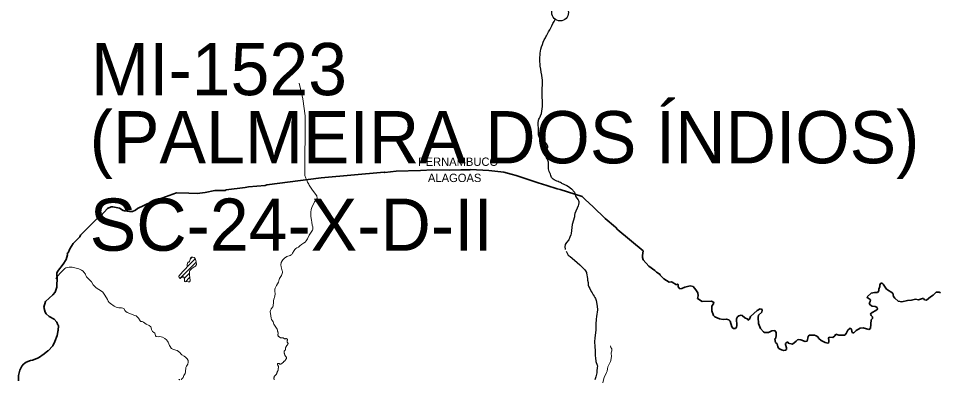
# Model space of a CAD drawing. Extents: x 553962 to 842807, y 8883888 to 9032388.
# Drawn here: x 608947 to 617774, y 8913066 to 8916524 of the extents above; entities that cross this region are included whole.
import ezdxf
from ezdxf.enums import TextEntityAlignment as Align

# ---------------------------------------------------------------- set-up
doc = ezdxf.new("R2010")
doc.units = 0
doc.header["$LTSCALE"] = 200
doc.linetypes.add('LONG_DASH_SHORT_DASH', pattern=[9.9, 6, -1.2, 1.5, -1.2])
doc.layers.add('6', color=7, linetype='Continuous', lineweight=13)

msp = doc.modelspace()

# ---------------------------------------------------------------- linework, layer by layer
at = {"layer": '6'}
for p, q in [((610565.7, 8914148.7), (610640.2, 8914223.2)), ((610592.8, 8914218.2), (610613.2, 8914238.6)), ((610494, 8914034.6), (610649.5, 8914190.1)), ((610536, 8914034.2), (610587.2, 8914085.3)), ((610547.2, 8914002.9), (610587.8, 8914043.4))]:
    msp.add_line(p, q, dxfattribs=at)
for points in [[(611636.1, 8915904.7), (611671, 8915753.7), (611694.2, 8915591.1), (611691.9, 8915020), (611701.8, 8914992.6)], [(611701.8, 8914992.6), (611709.5, 8914973.9), (611717.8, 8914957.2), (611728.7, 8914937.8), (611733.3, 8914927.2), (611738.5, 8914917.8), (611758.7, 8914890.3), (611784.6, 8914852.3), (611805.4, 8914826.5), (611808.3, 8914799.7), (611808.3, 8914799.7), (611808.3, 8914799.7), (611808.3, 8914799.7), (611785.5, 8914766.1), (611759.3, 8914712), (611752.6, 8914694.7), (611748.8, 8914667.4), (611748.6, 8914646.5), (611749.8, 8914628.6), (611755.2, 8914591.8), (611757.1, 8914572.4), (611762.5, 8914542.9), (611767.8, 8914528), (611767.7, 8914505.5), (611764.2, 8914496.9), (611758.8, 8914486.9), (611732.2, 8914447.5), (611716.2, 8914412.1), (611704.3, 8914394.9), (611693.1, 8914382.8), (611678.9, 8914371), (611658.2, 8914357.9), (611644, 8914347.7), (611629.4, 8914333.4), (611613.3, 8914326.6), (611603.6, 8914319.1), (611594.8, 8914310.6), (611588.4, 8914302.7), (611574.1, 8914274.6), (611566.6, 8914264.4), (611559.3, 8914258.5), (611551.8, 8914254.4), (611541, 8914251), (611528.6, 8914248.7), (611519.9, 8914244.7), (611496.5, 8914227.1), (611480.9, 8914211.8), (611472.7, 8914202), (611463.8, 8914186.4), (611462.7, 8914163.8), (611465.1, 8914144.4), (611472.2, 8914118.5), (611474.6, 8914105.9), (611476.2, 8914102), (611476.4, 8914091.2), (611475.1, 8914081.1), (611472.1, 8914071.7), (611467.5, 8914062.4), (611449.6, 8914032.3), (611446.1, 8914024.2), (611437.7, 8913996.9), (611420.2, 8913966.8), (611420.2, 8913966.8), (611408.7, 8913942.1), (611405.2, 8913932.8)], [(610550.1, 8914128.2), (610522.6, 8914099.6), (610485.2, 8914054.4), (610484.5, 8914051.4), (610485.8, 8914043.6), (610490.9, 8914038.7), (610495.7, 8914032.3), (610498.2, 8914032.8), (610503.2, 8914038.6), (610511.3, 8914041.6), (610520, 8914049.9), (610522.6, 8914050.8), (610526.2, 8914050.7), (610528.6, 8914048), (610536.9, 8914032.6), (610538.2, 8914010.4), (610539.8, 8914005.3), (610541.1, 8914003.4), (610572.1, 8914000.6), (610584.6, 8914001.8), (610587.4, 8914003), (610591.6, 8914010.9), (610591.8, 8914024.6), (610588.8, 8914032.4), (610588, 8914036.4), (610586.7, 8914070.3), (610587.8, 8914099.9), (610590.6, 8914109.6), (610593.7, 8914113.9), (610608, 8914127.7), (610618.3, 8914134.6), (610625.4, 8914140.7), (610632.9, 8914144.4), (610642.7, 8914150.8), (610652.1, 8914166.7), (610649.1, 8914194), (610643.6, 8914215.7), (610640.1, 8914223.4), (610630.2, 8914235.9), (610618.4, 8914238.7)], [(610618.4, 8914238.7), (610613.1, 8914238.6), (610606, 8914236.5), (610596.3, 8914228.7), (610594.6, 8914224.8), (610586.9, 8914195.9), (610580.3, 8914189.7), (610574.4, 8914190.9), (610570.6, 8914185.2), (610568.3, 8914176.6), (610564.4, 8914166.3), (610563.7, 8914158.5), (610565.8, 8914148.4), (610564.8, 8914145.3), (610550.1, 8914128.2)], [(609304.8, 8914031.3), (609316.3, 8914047), (609328.2, 8914061), (609345.4, 8914085), (609380.9, 8914119.9), (609391.6, 8914128.4), (609400.3, 8914134.1), (609417.9, 8914140.3)], [(609417.9, 8914140.3), (609432.3, 8914143), (609446.8, 8914143.1), (609462, 8914141.3), (609500.2, 8914133.9), (609525, 8914125.2), (609551.2, 8914114.5), (609565.8, 8914103.2), (609574.5, 8914094.8), (609590.7, 8914075.3), (609593.5, 8914063.3), (609599.2, 8914050.6), (609647.6, 8914002.6), (609664.4, 8913973.8), (609675.8, 8913959.2), (609691.7, 8913944.3), (609718.8, 8913929.2), (609744.3, 8913912.2), (609754.5, 8913902), (609775.4, 8913874.4), (609799.6, 8913831.8), (609808, 8913815.2), (609816.3, 8913803.9), (609827.9, 8913793.1), (609863.5, 8913769.2), (609883, 8913759.4), (609908.5, 8913753.4), (609934, 8913752.3), (609948.3, 8913750), (609960, 8913741.4), (609967.7, 8913728.2), (609976.3, 8913717.3), (609987.7, 8913708.8), (610063.1, 8913680.4), (610075.6, 8913674.7), (610087.9, 8913664), (610096.3, 8913653.3), (610112.7, 8913629.2), (610116, 8913625.7), (610120.4, 8913623.2), (610133.8, 8913620.9), (610145.7, 8913616.5), (610170.2, 8913594.9), (610199.2, 8913582.2), (610214.4, 8913569.6), (610219.3, 8913560.4), (610223.4, 8913545.4), (610230.4, 8913527.1), (610232.1, 8913525.3), (610240.4, 8913521), (610255.3, 8913511.4), (610259.1, 8913488.4), (610261.4, 8913484.1), (610266.4, 8913478.2), (610271.4, 8913476.7), (610286, 8913476.2), (610299.6, 8913477.2), (610314.8, 8913475.2), (610327.5, 8913471.4), (610351.4, 8913457.7), (610364.5, 8913445.8), (610374.8, 8913433.9), (610381.7, 8913423.5), (610381.7, 8913423.5), (610389.1, 8913409.2)], [(611405.2, 8913932.8), (611404.3, 8913919.3), (611405.3, 8913904.8), (611407.2, 8913893.3), (611407.4, 8913883.2), (611405, 8913868.1), (611400.2, 8913852.2), (611396.6, 8913845.8), (611394.4, 8913837.1), (611392.4, 8913819.2), (611392.1, 8913798.3), (611389.3, 8913781), (611388.7, 8913768.9), (611385.8, 8913762.7), (611369.2, 8913742.2), (611367.3, 8913738.6), (611366.3, 8913734.3), (611360.9, 8913727.5), (611358.2, 8913718), (611357.9, 8913713.9), (611361.9, 8913696.8), (611368.6, 8913655.1), (611372.9, 8913641.6), (611381.2, 8913629.6), (611387.6, 8913616.9), (611394.3, 8913594.7), (611425.5, 8913547), (611428, 8913539.7)], [(611428, 8913539.7), (611428.7, 8913537), (611429.4, 8913534.2), (611430, 8913531.7), (611431, 8913529.4), (611431.9, 8913527), (611432, 8913525.2), (611432.7, 8913522.8), (611433.4, 8913520.1), (611433.8, 8913517.5), (611434.4, 8913515), (611435.1, 8913512.4), (611435.7, 8913509.5), (611435.7, 8913506.8), (611435.5, 8913504.3), (611434.9, 8913501.7), (611434.3, 8913499.2), (611433.8, 8913496.3), (611433.7, 8913493.8), (611433.8, 8913491.1), (611434.6, 8913488.2), (611435.4, 8913485.7), (611436.1, 8913482.5), (611437.5, 8913480.3), (611439.4, 8913478.3), (611441.8, 8913477), (611444.5, 8913476.4), (611446.8, 8913474.9), (611448.8, 8913472.9), (611450.7, 8913470.9), (611452.7, 8913468.9), (611454.9, 8913467), (611457.3, 8913465.7), (611460.4, 8913464.9), (611463, 8913465.2), (611465.5, 8913465.8), (611468.2, 8913466.4), (611470.9, 8913466.6), (611473.5, 8913466.6), (611476.2, 8913466.6), (611478.8, 8913466.4), (611481.7, 8913466.1), (611484.9, 8913464.2), (611487.1, 8913462.7), (611489, 8913461), (611491.2, 8913459.4), (611493.2, 8913457.7), (611495.6, 8913456.4), (611498.5, 8913456), (611501.1, 8913456), (611503.7, 8913456.2), (611506.5, 8913456.8), (611509.3, 8913457.7), (611512, 8913458.6), (611514.6, 8913458.4), (611517.1, 8913457.1), (611519.3, 8913455.5), (611521.2, 8913453.8), (611522.9, 8913451.8), (611523.8, 8913450.6)], [(611523.8, 8913450.6), (611525.4, 8913446.9), (611525.5, 8913444), (611524.6, 8913441.6), (611522.9, 8913439.5), (611521.7, 8913437), (611520.6, 8913434.1), (611520.6, 8913431.2), (611520.6, 8913428.1), (611521.6, 8913425.5), (611523.2, 8913423.3), (611524.9, 8913421.3), (611526.6, 8913419.5), (611528.4, 8913417.5), (611530, 8913415.4), (611530.8, 8913412.9), (611530.7, 8913409.9), (611529.8, 8913407.3), (611528.4, 8913404.8), (611527.3, 8913402.4), (611526.1, 8913400.1), (611523.9, 8913398), (611521.4, 8913396.4), (611519.7, 8913394.6), (611518.1, 8913392.3), (611516.8, 8913389.9), (611515.6, 8913387.5), (611514.4, 8913385.1), (611512.9, 8913382.6), (611511.6, 8913380.2), (611510.4, 8913377.8), (611508.9, 8913374.4), (611507.9, 8913371.9), (611507.1, 8913369.3), (611506.2, 8913366.7), (611505.4, 8913364.2), (611505.2, 8913361.7), (611505.2, 8913359.2), (611505.4, 8913356.3), (611505.8, 8913353.8), (611505.5, 8913351.2), (611504.2, 8913348.8), (611502.8, 8913346.7), (611501.1, 8913344.8), (611498.7, 8913342.8), (611496.5, 8913341.3), (611494.8, 8913339.3), (611493.6, 8913337.1), (611493.5, 8913334.4), (611493.8, 8913331.9), (611493.8, 8913328.8), (611493.8, 8913326.2), (611493.8, 8913323.6), (611493.8, 8913320.8), (611494.2, 8913318), (611495.1, 8913315.3), (611496.4, 8913312.1), (611497.2, 8913309.5), (611498, 8913306.9), (611499.1, 8913304.3), (611500, 8913302), (611501.1, 8913299.2), (611502, 8913296.4), (611503.1, 8913293.8), (611504.4, 8913291.4)], [(610389.1, 8913409.2), (610395.4, 8913393.2), (610401.3, 8913381.1), (610409.7, 8913367.4), (610414, 8913362.1), (610427.1, 8913356), (610453.7, 8913346.8), (610468.8, 8913342.4), (610480.8, 8913335.7), (610492.2, 8913325.5), (610503.7, 8913311.6), (610513.8, 8913301.2), (610536.1, 8913288.8), (610548.6, 8913279.7), (610553.6, 8913275), (610564.1, 8913262.7), (610572.3, 8913247.7), (610574, 8913236.7), (610573.8, 8913232.5), (610569.3, 8913214.6), (610556.1, 8913194.1), (610551.1, 8913181.3), (610549.8, 8913168.7), (610549.5, 8913152.5), (610547.4, 8913140.6), (610543.5, 8913125.3), (610537.7, 8913112.6), (610533.2, 8913105.3), (610525.4, 8913084.2)], [(614620.1, 8913388.5), (614624.9, 8913373.7), (614631.9, 8913361.2), (614634.6, 8913353.9), (614634.5, 8913342.2), (614625.8, 8913322.2), (614625.8, 8913309.6), (614626.6, 8913305.2), (614628.8, 8913299.8), (614629, 8913291), (614622.6, 8913249.5), (614619.8, 8913237.7), (614614.5, 8913226.6), (614606.9, 8913214.3), (614596, 8913186.5), (614591, 8913166.9), (614587, 8913146.5), (614583.2, 8913134.8), (614574.9, 8913115.8), (614563.6, 8913095.4), (614555.5, 8913074.3), (614545.5, 8913034.2)], [(614620.1, 8913388.5), (614624.9, 8913373.7), (614631.9, 8913361.2), (614634.6, 8913353.9), (614634.5, 8913342.2), (614625.8, 8913322.2), (614625.8, 8913309.6), (614626.6, 8913305.2), (614628.8, 8913299.8), (614629, 8913291), (614622.6, 8913249.5), (614619.8, 8913237.7), (614614.5, 8913226.6), (614606.9, 8913214.3), (614596, 8913186.5), (614591, 8913166.9), (614587, 8913146.5), (614583.2, 8913134.8), (614574.9, 8913115.8), (614563.6, 8913095.4), (614555.5, 8913074.3), (614545.5, 8913034.2)], [(611504.4, 8913291.4), (611506.1, 8913289.1), (611507.8, 8913287.2), (611509.6, 8913285.3), (611511.5, 8913283), (611513.4, 8913280.6), (611515.3, 8913278.2), (611516.3, 8913275.7), (611516.2, 8913273.1), (611515.8, 8913270.5), (611515, 8913267.9), (611513.8, 8913265.1), (611512.2, 8913263), (611510.6, 8913260.8), (611509, 8913258.3), (611507.6, 8913255.6), (611505.9, 8913253), (611504.3, 8913251), (611502.6, 8913248.5), (611500.7, 8913246.3), (611498.7, 8913244.6), (611496.5, 8913242.9), (611494.1, 8913241.4), (611491.5, 8913239.6), (611489.4, 8913237.7), (611487.3, 8913235.2), (611485.6, 8913233), (611483.6, 8913230.5), (611481.8, 8913228.6), (611480, 8913226.6), (611478.2, 8913224.8), (611475.6, 8913222.2), (611473.4, 8913220.8), (611471.2, 8913219.4), (611468.9, 8913217.9), (611465.8, 8913216.3), (611463, 8913214.8)], [(611463, 8913214.8), (611460.6, 8913213.6), (611458, 8913212.7), (611455.2, 8913212.1), (611452.7, 8913212.4), (611450.5, 8913213.7), (611448.5, 8913215.6), (611446.8, 8913218), (611445.3, 8913220), (611441.8, 8913220.3), (611438.9, 8913220.2), (611436.2, 8913219.8), (611433.4, 8913219), (611431, 8913217.9), (611429.9, 8913215.5), (611429.9, 8913212.7), (611429.9, 8913210.1), (611430.6, 8913207.5), (611432.2, 8913205.1), (611433.5, 8913202.6), (611434.5, 8913200.1), (611435.5, 8913197.2), (611436.8, 8913194.7), (611438.5, 8913192.3), (611439.6, 8913189.6), (611440, 8913186.4), (611439.9, 8913183.7), (611439.6, 8913180.8), (611438.8, 8913178.3), (611437.8, 8913175.9), (611437.3, 8913173.3), (611436.7, 8913170.4), (611436.1, 8913167.8), (611435.5, 8913165), (611435.2, 8913162), (611435, 8913159.2), (611434.7, 8913154.3), (611434.7, 8913154.1), (611433.7, 8913152.4), (611432.9, 8913149.8), (611431.8, 8913147.4), (611430.2, 8913145.2), (611429, 8913143), (611427.7, 8913140.3), (611426.5, 8913137.7), (611425.6, 8913135), (611424.8, 8913132.1), (611424, 8913129.5), (611423.2, 8913127.1), (611422, 8913124.6), (611420.9, 8913122.1), (611420.1, 8913119.7), (611419, 8913117), (611417.4, 8913115), (611415.2, 8913113.4), (611413.2, 8913111.8), (611411.3, 8913110), (611409.6, 8913108.1), (611408.1, 8913105.9), (611406.4, 8913103.6), (611404.7, 8913101.5), (611402.4, 8913099.4), (611400.6, 8913097.7), (611398.9, 8913095.4), (611397.7, 8913092.6)], [(610492.6, 8913063.5), (610491.2, 8913065.9), (610489, 8913067.2), (610486.6, 8913066.3), (610484.7, 8913064.7)], [(610525.4, 8913084.2), (610525.2, 8913084), (610523.8, 8913081.7), (610522, 8913079.7), (610520.1, 8913078.1), (610517.9, 8913076.8), (610516.1, 8913074.9), (610514.3, 8913072.9), (610512.9, 8913070.6), (610511.1, 8913068.7), (610509, 8913066.9), (610506.9, 8913065.2)], [(611395.7, 8913078.9), (611395.6, 8913076.5), (611395.7, 8913073.8), (611396, 8913071.1), (611396.2, 8913068.6), (611397, 8913066), (611398.5, 8913063.9)], [(611397.7, 8913092.6), (611396.8, 8913089.8), (611396.4, 8913087.2), (611396, 8913084.5), (611395.7, 8913081.9), (611395.7, 8913079.2), (611395.7, 8913078.9)]]:
    msp.add_lwpolyline(points, dxfattribs=at)
at = {"layer": '6', "linetype": 'LONG_DASH_SHORT_DASH', "lineweight": 35}
for points in [[(609417, 8914259.9), (609414.5, 8914271.5), (609423.4, 8914278), (609438.5, 8914317.1), (609470.2, 8914368), (609534.8, 8914432.1), (609542.7, 8914447.8), (609726.2, 8914632.2), (609735.6, 8914633.7), (609801.8, 8914705.2), (609834.3, 8914720.4), (609853.1, 8914720.4), (609915.1, 8914705.6), (609951.4, 8914683.3), (609956.6, 8914684.2), (609962.2, 8914680.3), (610012.3, 8914673.4), (610039, 8914675), (610068.6, 8914686.7), (610088.4, 8914702.4), (610215.4, 8914764.3), (610462.8, 8914853.2), (610579.4, 8914851.9), (610659.1, 8914847.2), (610736.4, 8914857.9), (610829, 8914875.5), (610927.4, 8914877.4), (610939, 8914881.5), (611120.3, 8914903.8), (611152.1, 8914910.7), (611312, 8914924.8), (611328.8, 8914929.5), (611846.5, 8914996.4), (612450.8, 8915051.7), (612456.6, 8915048.8), (612566.7, 8915060.4), (612801.4, 8915066.3)], [(612801.4, 8915066.3), (612801.4, 8915066.3), (612917.6, 8915073.7), (613074.1, 8915071.3), (613187.3, 8915075.4), (613275.3, 8915075.1), (613277.6, 8915078.3), (613454.2, 8915067.7), (613598.2, 8915052.7), (613669.1, 8915033.8), (613716.2, 8915018.8), (613926, 8914950.1), (614011.9, 8914925.2), (614110.4, 8914892.2), (614138, 8914884.1), (614349.8, 8914819.3), (614378.6, 8914788.4), (614454.1, 8914720.6), (614569.5, 8914609.1), (614667.9, 8914523.4), (614691.4, 8914498.4), (614934.5, 8914297.2), (614926, 8914253.5), (614926.6, 8914235.8), (614934.1, 8914212.7), (614988.2, 8914151.7), (615044.9, 8914110.5), (615062.4, 8914093.5), (615094.9, 8914071.6), (615095.4, 8914066.5), (615131.7, 8914029.6), (615182, 8913997.8), (615202.2, 8914003), (615212.9, 8913999.6), (615254.5, 8913972.2), (615262.9, 8913981.5), (615269.5, 8913976), (615267.8, 8913953.3), (615285, 8913934.8), (615303, 8913937), (615333.5, 8913951.1), (615382.6, 8913962.7), (615413, 8913957.6), (615439.6, 8913924.7), (615458.4, 8913895.8), (615460.8, 8913867.6), (615455.3, 8913841), (615498, 8913813.2), (615587.6, 8913815.1), (615607.9, 8913805.3), (615609.2, 8913797.1), (615590.4, 8913767.9), (615593.1, 8913723.7), (615608.8, 8913678.4), (615621.4, 8913665.8), (615666.1, 8913648.6), (615700.6, 8913642.3), (615731.2, 8913643.1), (615755.6, 8913636.8), (615768.2, 8913623.5), (615784.4, 8913569.2), (615797.2, 8913555.9), (615817.5, 8913555.9), (615828.6, 8913566.1), (615832.5, 8913584.8), (615828.6, 8913645.9), (615837.2, 8913665.5), (615849.7, 8913677.2), (615872.5, 8913682.7), (615883.4, 8913678), (615906.2, 8913656.1), (615935.6, 8913643.9), (615937.2, 8913633), (615951.3, 8913644), (615963.1, 8913670.6), (616027, 8913728.4), (616054.1, 8913744.3), (616072.5, 8913737.9), (616075.1, 8913731.3), (616071.8, 8913710.6), (616040.1, 8913682), (616037, 8913660.1), (616038.5, 8913603.8), (616058.5, 8913554.9), (616086, 8913521.2), (616096.2, 8913514.9), (616133, 8913515.7), (616167.5, 8913533.7), (616194.4, 8913535.4), (616208.9, 8913517.8), (616208.9, 8913491.7), (616204.6, 8913462.2), (616196.4, 8913454.6), (616201.1, 8913420.2), (616217.1, 8913406.8), (616225.2, 8913379.8), (616234.7, 8913362.6)], [(608946.9, 8913054.2), (608947.5, 8913104.1), (608959.7, 8913156.7), (608979, 8913193.9), (608994.6, 8913214.2), (609021.3, 8913233.8), (609062.8, 8913248.6), (609080.9, 8913251), (609139.7, 8913275.3), (609195.1, 8913310.8), (609228, 8913340.4), (609232.6, 8913340.3), (609276.6, 8913389.1), (609297.3, 8913429.6), (609318.1, 8913487), (609324.7, 8913524.3), (609323.1, 8913528.6), (609328.6, 8913536.8), (609332, 8913584.8), (609323.1, 8913590.8), (609315.6, 8913614.7), (609290.5, 8913645.2), (609240.2, 8913670.2), (609212.4, 8913694.1), (609201.8, 8913711), (609190.8, 8913757.9), (609207.3, 8913814.3), (609277.5, 8913876.2), (609298.7, 8913903.7), (609314.4, 8913949), (609314.4, 8913981.9), (609319.5, 8914018.2), (609315.7, 8914084.9), (609322.5, 8914099.7), (609375.2, 8914169.3), (609404.5, 8914214.5), (609417, 8914259.9)], [(616234.7, 8913362.6), (616259.5, 8913349.8), (616259.5, 8913349.8), (616280.9, 8913345.4), (616298.6, 8913346.6), (616305.9, 8913354.1), (616306.7, 8913369.1), (616296, 8913399.9), (616296.9, 8913409.7), (616314.5, 8913422.3), (616323.8, 8913423.9), (616324, 8913412.8), (616363.5, 8913406.2), (616400.1, 8913433.3), (616411.5, 8913446.5), (616425.2, 8913450), (616444, 8913446.9), (616486.4, 8913430.5), (616504.3, 8913434.4), (616513.8, 8913477.4), (616525.6, 8913490.7), (616576.1, 8913489.6), (616591.8, 8913484.8), (616606.7, 8913474.7), (616616.1, 8913458.2), (616639.7, 8913441), (616677.7, 8913419.5), (616702.8, 8913414.1), (616712.9, 8913419.5), (616713.7, 8913439.8), (616709.1, 8913462.4), (616717.3, 8913472.4), (616751.1, 8913469.9), (616769.5, 8913485.1), (616779.8, 8913499.1), (616809.5, 8913489.6), (616864.6, 8913491.7), (616880.3, 8913505.5), (616896.3, 8913537.7), (616917.5, 8913556.4), (616929.6, 8913547.8), (616933.9, 8913525.2), (616939.7, 8913514.7), (616952.2, 8913513.8), (616973.8, 8913536.7), (617013.7, 8913557.3), (617040.2, 8913561.6), (617095.3, 8913546.6), (617112.1, 8913555.6), (617119.3, 8913636.9), (617131.8, 8913650.4), (617131, 8913666.7), (617117.7, 8913678.5), (617111.1, 8913691.4), (617119.7, 8913700.8), (617172.2, 8913732.9), (617178.4, 8913742.9), (617176.8, 8913756.4), (617157.3, 8913765.7), (617128.2, 8913768.1), (617113.4, 8913777.5), (617097.9, 8913795.2), (617107.9, 8913813.5), (617112.2, 8913828.7), (617105.9, 8913836.5), (617083.2, 8913846.7), (617080.1, 8913857.7), (617118.5, 8913892.3), (617151.8, 8913900.6), (617179.3, 8913900.6), (617191, 8913916.2), (617191.8, 8913931.9), (617201.2, 8913956.9), (617201.2, 8913974.1), (617211.4, 8913988.2), (617223.2, 8913988.2), (617234.9, 8913980.4), (617265.2, 8913929.9), (617324.7, 8913892.4), (617331.9, 8913862.3), (617346.5, 8913844.8), (617377.2, 8913817.2), (617412.6, 8913809.8), (617467.4, 8913823.1), (617504.3, 8913824.6), (617542.5, 8913836.1), (617571.2, 8913828.7), (617610.4, 8913841.2), (617619, 8913840.4), (617630.8, 8913828.7), (617649.5, 8913824.8), (617687.6, 8913857.3), (617713.4, 8913872.9), (617731.5, 8913893.3), (617742.4, 8913901.1), (617769.8, 8913902.7), (617781.7, 8913895.6)]]:
    msp.add_lwpolyline(points, dxfattribs=at)
at = {"layer": '6', "lineweight": 25}
for points in [[(614150.8, 8914946.8), (614203.4, 8914923.6), (614219.2, 8914914.1), (614248.1, 8914891.9), (614274.4, 8914859), (614285.4, 8914820.3), (614297.9, 8914802), (614310.3, 8914787.6), (614314.4, 8914779.7), (614315.7, 8914772), (614315.9, 8914758.2), (614313.3, 8914740.9), (614309.4, 8914728.2), (614280.1, 8914656.7), (614276, 8914641.2), (614276.3, 8914628.6), (614275.7, 8914624.6), (614251.7, 8914550), (614243.4, 8914465), (614240.3, 8914452.2), (614231.3, 8914428.1), (614220.5, 8914404.5), (614198, 8914377.3), (614186.3, 8914359.4), (614184.7, 8914355.3), (614182, 8914339.1), (614187.1, 8914310.2)], [(614194.7, 8914296.6), (614216.1, 8914258.1), (614233.7, 8914242.9), (614276.3, 8914209.9), (614325.7, 8914164.7), (614338.8, 8914150.3), (614373.7, 8914115.3), (614379.8, 8914105.7)], [(614379.8, 8914105.7), (614390, 8914089.8), (614391.9, 8914083.3), (614400.1, 8914033.8), (614401.7, 8914017.4), (614405.8, 8913994.1), (614407.6, 8913968.3), (614413.2, 8913954.3), (614421.5, 8913936.7)], [(614421.5, 8913936.7), (614433.8, 8913910.3), (614443.7, 8913895.8), (614453.7, 8913878.4), (614464.4, 8913864.2), (614471.2, 8913852), (614475.8, 8913841.6), (614482.2, 8913821.7), (614494.2, 8913769.7), (614495.6, 8913732.6), (614485.3, 8913671.1), (614482.4, 8913644.9), (614480.7, 8913596), (614481.5, 8913550.2), (614480.9, 8913539.8), (614471, 8913465.6), (614467.5, 8913427.4), (614469.1, 8913381.7), (614468.8, 8913368.8), (614472.3, 8913352.8), (614472.6, 8913293), (614475.4, 8913274.7)], [(614475.4, 8913274.7), (614480.9, 8913239.2), (614493.8, 8913202.3), (614495, 8913196.5), (614492.8, 8913177.3), (614490.9, 8913148.1), (614488.3, 8913129.2), (614479, 8913090.6), (614470.3, 8913061.6)]]:
    msp.add_lwpolyline(points, dxfattribs=at)
msp.add_circle((614137.6, 8916580.5), 80.3, dxfattribs=at)
msp.add_spline([(614150.8, 8914946.8), (614106, 8914966.5), (614061.7, 8914993.4), (614044.2, 8915031), (614025.4, 8915082.1), (614026.7, 8915123.8), (614018.7, 8915166.8), (613997.1, 8915212.5), (614001.2, 8915255.5), (614018.7, 8915291.8), (614010.6, 8915320.1), (613970.2, 8915351), (613939.3, 8915383.2), (613929.9, 8915445.1), (613928.6, 8915515), (613931.3, 8915548.6), (613950.1, 8915591), (613968.9, 8915681.1), (613966.2, 8915794.1), (613967.6, 8915882.8), (613966.2, 8915952.8), (613947.4, 8916067.1), (613944.7, 8916151.8), (613954.1, 8916229.8), (613986.4, 8916318.6), (614006.6, 8916357.6), (614090, 8916512.3)], degree=3, dxfattribs=at)

# ---------------------------------------------------------------- texts
at = {"layer": '6'}
for s, p in [('MI-1523', (609642.6, 8915788.7)), ('(PALMEIRA DOS ÍNDIOS)', (609630, 8915136.3)), ('SC-24-X-D-II', (609630, 8914299.2))]:
    msp.add_text(s, height=500, dxfattribs=at).set_placement(p)
for s, p in [('PERNAMBUCO', (613160.6, 8915111.6)), ('ALAGOAS', (613127.1, 8914956.9))]:
    msp.add_text(s, height=80, dxfattribs=at).set_placement(p, align=Align.CENTER)

doc.saveas('drawing.dxf')
